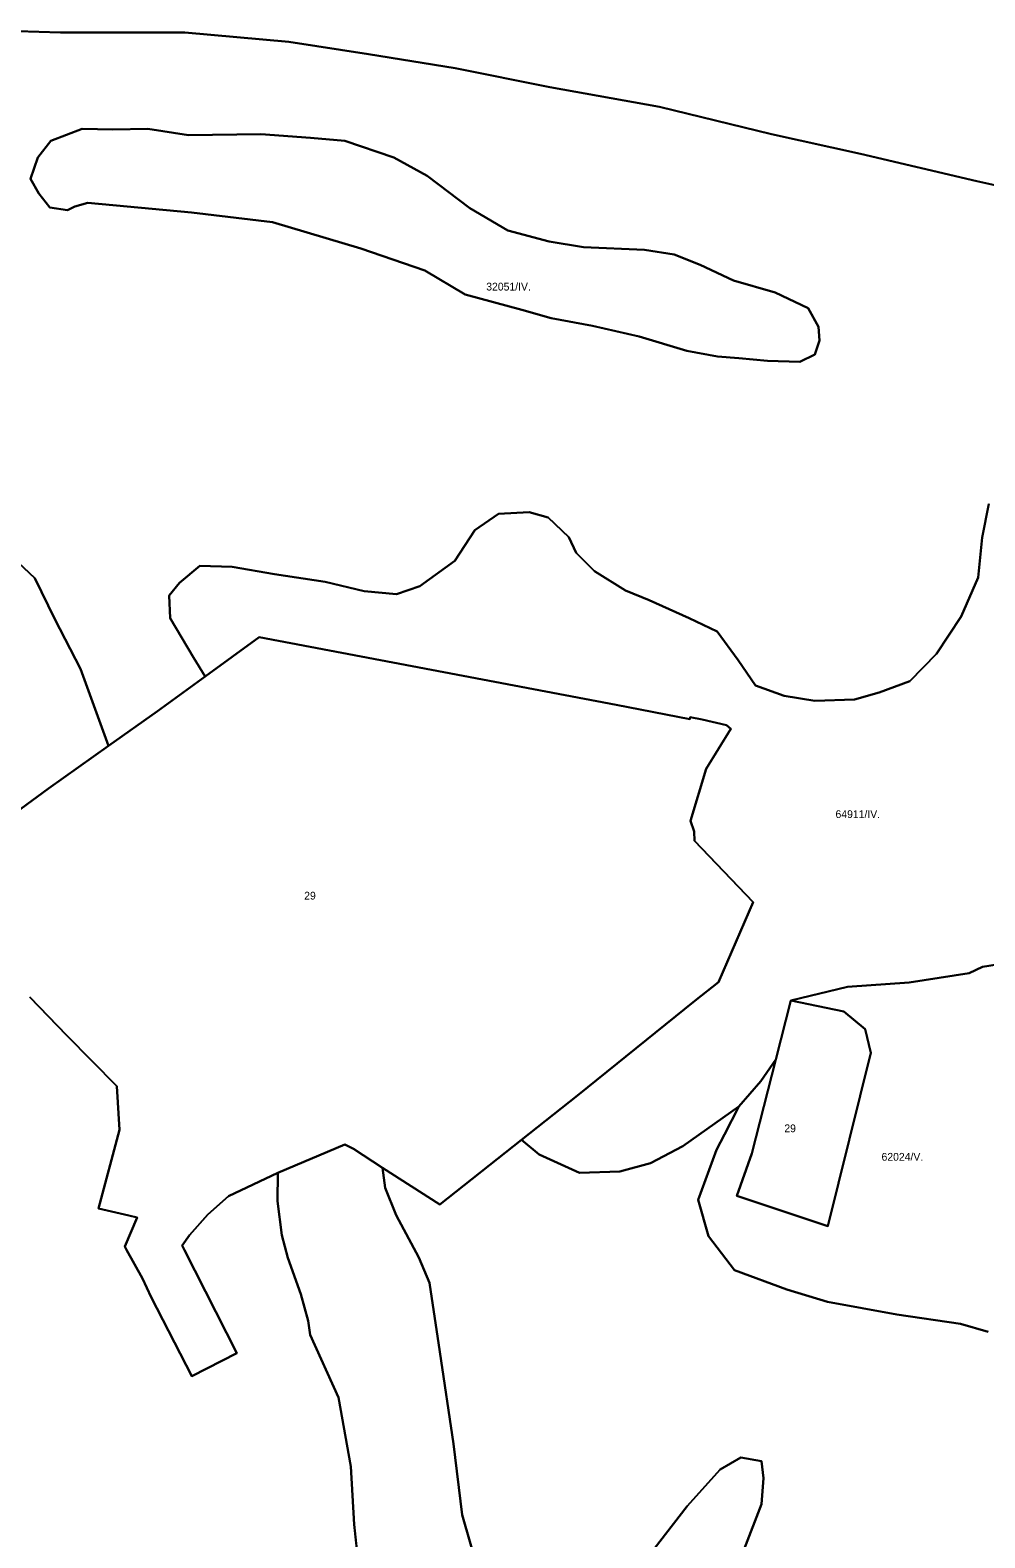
# Model space of a CAD drawing. Extents: x -521621 to -516761, y -1190184 to -1184927.
# Drawn here: x -519813 to -519322, y -1188092 to -1187318 of the extents above; entities that cross this region are included whole.
import ezdxf

# ---------------------------------------------------------------- set-up
doc = ezdxf.new("R2010")
doc.units = 0
doc.layers.add('BPEJ_s', color=7, linetype='Continuous')

msp = doc.modelspace()

# ---------------------------------------------------------------- linework, layer by layer
at = {"layer": 'BPEJ_s'}
for p, q in [((-519836.59, -1187317.66), (-519797.22, -1187318.93)), ((-519797.22, -1187318.93), (-519733.29, -1187318.93)), ((-519733.29, -1187318.93), (-519679.94, -1187323.59)), ((-519679.94, -1187323.59), (-519638.88, -1187329.95)), ((-519638.88, -1187329.95), (-519594.42, -1187337.15)), ((-519594.42, -1187337.15), (-519545.74, -1187346.89)), ((-519545.74, -1187346.89), (-519489.43, -1187357.06)), ((-519489.43, -1187357.06), (-519431.85, -1187371.04)), ((-519802.18, -1187374.46), (-519808.84, -1187383.02)), ((-519786.03, -1187368.28), (-519802.18, -1187374.46)), ((-519770.35, -1187368.75), (-519786.03, -1187368.28)), ((-519752.29, -1187368.28), (-519770.35, -1187368.75)), ((-519731.38, -1187371.61), (-519752.29, -1187368.28)), ((-519694.32, -1187371.13), (-519731.38, -1187371.61)), ((-519668.66, -1187373.03), (-519694.32, -1187371.13)), ((-519651.08, -1187374.46), (-519668.66, -1187373.03)), ((-519625.89, -1187383.02), (-519651.08, -1187374.46)), ((-519431.85, -1187371.04), (-519386.13, -1187381.21)), ((-519808.84, -1187383.02), (-519812.64, -1187393.96)), ((-519608.78, -1187392.53), (-519625.89, -1187383.02)), ((-519386.13, -1187381.21), (-519326.43, -1187395.19)), ((-519812.64, -1187393.96), (-519808.36, -1187401.56)), ((-519586.93, -1187409.17), (-519608.78, -1187392.53)), ((-519326.43, -1187395.19), (-519257, -1187410.86)), ((-519808.36, -1187401.56), (-519802.66, -1187408.69)), ((-519802.66, -1187408.69), (-519793.63, -1187410.12)), ((-519793.63, -1187410.12), (-519789.83, -1187408.22)), ((-519789.83, -1187408.22), (-519783.04, -1187406.37)), ((-519783.04, -1187406.37), (-519729.87, -1187411.26)), ((-519729.87, -1187411.26), (-519688.33, -1187416.31)), ((-519567.44, -1187420.58), (-519586.93, -1187409.17)), ((-519688.33, -1187416.31), (-519642.89, -1187429.9)), ((-519546.06, -1187426.29), (-519567.44, -1187420.58)), ((-519528.48, -1187429.14), (-519546.06, -1187426.29)), ((-519497.12, -1187430.57), (-519528.48, -1187429.14)), ((-519642.89, -1187429.9), (-519610.01, -1187441.1)), ((-519481.91, -1187432.94), (-519497.12, -1187430.57)), ((-519468.6, -1187438.17), (-519481.91, -1187432.94)), ((-519610.01, -1187441.1), (-519589.34, -1187453.42)), ((-519451.5, -1187446.26), (-519468.6, -1187438.17)), ((-519430.11, -1187452.44), (-519451.5, -1187446.26)), ((-519413.01, -1187460.52), (-519430.11, -1187452.44)), ((-519589.34, -1187453.42), (-519560.09, -1187461.28)), ((-519407.78, -1187470.03), (-519413.01, -1187460.52)), ((-519560.09, -1187461.28), (-519545.1, -1187465.54)), ((-519545.1, -1187465.54), (-519523.8, -1187469.49)), ((-519523.8, -1187469.49), (-519499.82, -1187475.02)), ((-519499.82, -1187475.02), (-519475.49, -1187482.38)), ((-519407.31, -1187477.16), (-519407.78, -1187470.03)), ((-519475.49, -1187482.38), (-519459.58, -1187485.25)), ((-519409.68, -1187484.3), (-519407.31, -1187477.16)), ((-519459.58, -1187485.25), (-519448.65, -1187486.2)), ((-519448.65, -1187486.2), (-519433.92, -1187487.62)), ((-519433.92, -1187487.62), (-519417.28, -1187488.1)), ((-519417.28, -1187488.1), (-519409.68, -1187484.3)), ((-519320.31, -1187560.93), (-519323.61, -1187578.33)), ((-519572.15, -1187566.12), (-519584.35, -1187574.45)), ((-519556.33, -1187565.29), (-519572.15, -1187566.12)), ((-519546.63, -1187568.06), (-519556.33, -1187565.29)), ((-519536.09, -1187578.06), (-519546.63, -1187568.06)), ((-519584.35, -1187574.45), (-519594.61, -1187590.27)), ((-519532.2, -1187586.11), (-519536.09, -1187578.06)), ((-519323.61, -1187578.33), (-519325.83, -1187598.87)), ((-519810.41, -1187599.15), (-519824.56, -1187585.83)), ((-519594.61, -1187590.27), (-519612.64, -1187603.31)), ((-519522.77, -1187595.54), (-519532.2, -1187586.11)), ((-519800.15, -1187620.24), (-519810.41, -1187599.15)), ((-519725.54, -1187592.77), (-519736.07, -1187601.65)), ((-519708.89, -1187593.32), (-519725.54, -1187592.77)), ((-519687.26, -1187597.21), (-519708.89, -1187593.32)), ((-519661.18, -1187601.09), (-519687.26, -1187597.21)), ((-519506.96, -1187605.53), (-519522.77, -1187595.54)), ((-519325.83, -1187598.87), (-519334.43, -1187618.86)), ((-519736.07, -1187601.65), (-519741.34, -1187608.03)), ((-519641.21, -1187605.81), (-519661.18, -1187601.09)), ((-519624.57, -1187607.48), (-519641.21, -1187605.81)), ((-519612.64, -1187603.31), (-519624.57, -1187607.48)), ((-519494.76, -1187610.53), (-519506.96, -1187605.53)), ((-519741.34, -1187608.03), (-519740.79, -1187619.69)), ((-519474.23, -1187619.69), (-519494.76, -1187610.53)), ((-519786.83, -1187645.78), (-519800.15, -1187620.24)), ((-519740.79, -1187619.69), (-519728.86, -1187639.95)), ((-519459.81, -1187626.63), (-519474.23, -1187619.69)), ((-519334.43, -1187618.86), (-519347.19, -1187638.01)), ((-519448.99, -1187641.34), (-519459.81, -1187626.63)), ((-519347.19, -1187638.01), (-519360.78, -1187652.16)), ((-519772.51, -1187685.38), (-519786.83, -1187645.78)), ((-519728.86, -1187639.95), (-519722.87, -1187649.69)), ((-519440.11, -1187654.38), (-519448.99, -1187641.34)), ((-519722.87, -1187649.69), (-519747.38, -1187667.46)), ((-519360.78, -1187652.16), (-519376.59, -1187657.99)), ((-519425.41, -1187659.66), (-519440.11, -1187654.38)), ((-519409.6, -1187662.15), (-519425.41, -1187659.66)), ((-519389.35, -1187661.6), (-519409.6, -1187662.15)), ((-519376.59, -1187657.99), (-519389.35, -1187661.6)), ((-519747.38, -1187667.46), (-519772.51, -1187685.38)), ((-519812.86, -1187814.51), (-519793.87, -1187834.17)), ((-519793.87, -1187834.17), (-519768.25, -1187860.13)), ((-519768.25, -1187860.13), (-519766.91, -1187882.58)), ((-519766.91, -1187882.58), (-519777.62, -1187923.04)), ((-519710.91, -1187916.7), (-519685.53, -1187904.73)), ((-519685.53, -1187904.73), (-519685.65, -1187919.2)), ((-519721.39, -1187926.04), (-519710.91, -1187916.7)), ((-519777.62, -1187923.04), (-519761.98, -1187926.53)), ((-519685.65, -1187919.2), (-519683.42, -1187936.76)), ((-519757.81, -1187927.71), (-519764.18, -1187942.61)), ((-519761.98, -1187926.53), (-519757.81, -1187927.71)), ((-519730.89, -1187936.69), (-519721.39, -1187926.04)), ((-519734.58, -1187942.03), (-519730.89, -1187936.69)), ((-519683.42, -1187936.76), (-519680.31, -1187948.33)), ((-519764.18, -1187942.61), (-519763.17, -1187944.17)), ((-519763.17, -1187944.17), (-519755.07, -1187958.91)), ((-519733.51, -1187944.38), (-519734.58, -1187942.03)), ((-519706.62, -1187997.35), (-519733.51, -1187944.38)), ((-519680.31, -1187948.33), (-519673.65, -1187967)), ((-519755.07, -1187958.91), (-519750.58, -1187968.52)), ((-519750.58, -1187968.52), (-519729.67, -1188009.1)), ((-519673.65, -1187967), (-519669.87, -1187980.79)), ((-519669.87, -1187980.79), (-519668.9, -1187987.88)), ((-519668.9, -1187987.88), (-519654.42, -1188020.09)), ((-519729.67, -1188009.1), (-519706.62, -1187997.35)), ((-519654.42, -1188020.09), (-519647.98, -1188055.52)), ((-519647.98, -1188055.52), (-519646.37, -1188085.32)), ((-519646.37, -1188085.32), (-519639.13, -1188151.35))]:
    msp.add_line(p, q, dxfattribs=at)
for points in [[(-519257, -1187410.86), (-519326.43, -1187395.19), (-519386.13, -1187381.21), (-519431.85, -1187371.04), (-519489.43, -1187357.06), (-519545.74, -1187346.89), (-519594.42, -1187337.15), (-519638.88, -1187329.95), (-519679.94, -1187323.59), (-519733.29, -1187318.93), (-519797.22, -1187318.93), (-519836.59, -1187317.66)], [(-519303.15, -1187795.52), (-519323.47, -1187798.9), (-519330.33, -1187802.04), (-519361.24, -1187806.96), (-519392.85, -1187809.07), (-519422.03, -1187816.17), (-519429.72, -1187846.45), (-519437.46, -1187857.57), (-519448.7, -1187870.58), (-519477.51, -1187890.97), (-519494.02, -1187899.75), (-519509.82, -1187903.97), (-519530.55, -1187904.67), (-519551.27, -1187895.18), (-519560.37, -1187887.81), (-519531.55, -1187865), (-519471.37, -1187816.27), (-519459.2, -1187806.79), (-519441.4, -1187765.6), (-519471.42, -1187734.06), (-519471.72, -1187729.26), (-519473.52, -1187723.85), (-519465.47, -1187697.1), (-519452.88, -1187676.55), (-519455.1, -1187674.65), (-519467.57, -1187671.74), (-519473.61, -1187670.59), (-519473.79, -1187671.56), (-519511.79, -1187664.33), (-519695.16, -1187629.58), (-519722.87, -1187649.69), (-519728.86, -1187639.95), (-519740.79, -1187619.69), (-519741.34, -1187608.03), (-519736.07, -1187601.65), (-519725.54, -1187592.77), (-519708.89, -1187593.32), (-519687.26, -1187597.21), (-519661.18, -1187601.09), (-519641.21, -1187605.81), (-519624.57, -1187607.48), (-519612.64, -1187603.31), (-519594.61, -1187590.27), (-519584.35, -1187574.45), (-519572.15, -1187566.12), (-519556.33, -1187565.29), (-519546.63, -1187568.06), (-519536.09, -1187578.06), (-519532.2, -1187586.11), (-519522.77, -1187595.54), (-519506.96, -1187605.53), (-519494.76, -1187610.53), (-519474.23, -1187619.69), (-519459.81, -1187626.63), (-519448.99, -1187641.34), (-519440.11, -1187654.38), (-519425.41, -1187659.66), (-519409.6, -1187662.15), (-519389.35, -1187661.6), (-519376.59, -1187657.99), (-519360.78, -1187652.16), (-519347.19, -1187638.01), (-519334.43, -1187618.86), (-519325.83, -1187598.87), (-519323.61, -1187578.33), (-519320.31, -1187560.93)], [(-519824.56, -1187585.83), (-519810.41, -1187599.15), (-519800.15, -1187620.24), (-519786.83, -1187645.78), (-519772.51, -1187685.38), (-519803.25, -1187707.28), (-519826, -1187723.77)], [(-519826, -1187723.77), (-519803.25, -1187707.28), (-519772.51, -1187685.38), (-519747.38, -1187667.46), (-519722.87, -1187649.69), (-519695.16, -1187629.58), (-519511.79, -1187664.33), (-519473.79, -1187671.56), (-519473.61, -1187670.59), (-519467.57, -1187671.74), (-519455.1, -1187674.65), (-519452.88, -1187676.55), (-519465.47, -1187697.1), (-519473.52, -1187723.85), (-519471.72, -1187729.26), (-519471.42, -1187734.06), (-519441.4, -1187765.6), (-519459.2, -1187806.79), (-519471.37, -1187816.27), (-519531.55, -1187865), (-519560.37, -1187887.81), (-519602.33, -1187921.01), (-519631.66, -1187902.09), (-519646.68, -1187892.41), (-519651.15, -1187890.15), (-519685.53, -1187904.73), (-519710.91, -1187916.7), (-519721.39, -1187926.04), (-519730.89, -1187936.69), (-519734.58, -1187942.03), (-519733.51, -1187944.38), (-519706.62, -1187997.35), (-519729.67, -1188009.1), (-519750.58, -1187968.52), (-519755.07, -1187958.91), (-519763.17, -1187944.17), (-519764.18, -1187942.61), (-519757.81, -1187927.71), (-519761.98, -1187926.53), (-519777.62, -1187923.04), (-519766.91, -1187882.58), (-519768.25, -1187860.13), (-519793.87, -1187834.17), (-519812.86, -1187814.51)], [(-519320.55, -1187986.31), (-519334.84, -1187982.22), (-519367.49, -1187977.41), (-519403.06, -1187970.99), (-519424.06, -1187964.57), (-519450.88, -1187954.65), (-519464.29, -1187937.15), (-519469.54, -1187918.48), (-519460.21, -1187892.8), (-519456.08, -1187884.99), (-519448.7, -1187870.58), (-519437.46, -1187857.57), (-519429.72, -1187846.45), (-519441.99, -1187894.78), (-519449.8, -1187916.5), (-519402.93, -1187932.13), (-519380.8, -1187843.1), (-519383.84, -1187830.94), (-519394.69, -1187821.82), (-519422.03, -1187816.17), (-519392.85, -1187809.07), (-519361.24, -1187806.96), (-519330.33, -1187802.04), (-519323.47, -1187798.9), (-519303.15, -1187795.52)], [(-519581.87, -1188111.43), (-519590.76, -1188080.3), (-519595.2, -1188043.83), (-519602.31, -1187996.69), (-519607.65, -1187961.11), (-519613.1, -1187948.26), (-519624.69, -1187926.47), (-519630.31, -1187912.41), (-519631.66, -1187902.09), (-519602.33, -1187921.01), (-519560.37, -1187887.81), (-519551.27, -1187895.18), (-519530.55, -1187904.67), (-519509.82, -1187903.97), (-519494.02, -1187899.75), (-519477.51, -1187890.97), (-519448.7, -1187870.58), (-519456.08, -1187884.99), (-519460.21, -1187892.8), (-519469.54, -1187918.48), (-519464.29, -1187937.15), (-519450.88, -1187954.65), (-519424.06, -1187964.57), (-519403.06, -1187970.99), (-519367.49, -1187977.41), (-519334.84, -1187982.22), (-519320.55, -1187986.31)], [(-519639.13, -1188151.35), (-519646.37, -1188085.32), (-519647.98, -1188055.52), (-519654.42, -1188020.09), (-519668.9, -1187987.88), (-519669.87, -1187980.79), (-519673.65, -1187967), (-519680.31, -1187948.33), (-519683.42, -1187936.76), (-519685.65, -1187919.2), (-519685.53, -1187904.73), (-519651.15, -1187890.15), (-519646.68, -1187892.41), (-519631.66, -1187902.09), (-519630.31, -1187912.41), (-519624.69, -1187926.47), (-519613.1, -1187948.26), (-519607.65, -1187961.11), (-519602.31, -1187996.69), (-519595.2, -1188043.83), (-519590.76, -1188080.3), (-519581.87, -1188111.43)], [(-519445.87, -1188098.08), (-519436.98, -1188074.96), (-519436.09, -1188061.62), (-519436.98, -1188052.72), (-519447.65, -1188050.95), (-519458.31, -1188057.17), (-519475.2, -1188075.85), (-519499.2, -1188106.98)], [(-519499.2, -1188106.98), (-519475.2, -1188075.85), (-519458.31, -1188057.17), (-519447.65, -1188050.95), (-519436.98, -1188052.72), (-519436.09, -1188061.62), (-519436.98, -1188074.96), (-519445.87, -1188098.08)]]:
    msp.add_lwpolyline(points, dxfattribs=at)
for points in [[(-519770.35, -1187368.75), (-519752.29, -1187368.28), (-519731.38, -1187371.61), (-519694.32, -1187371.13), (-519668.66, -1187373.03), (-519651.08, -1187374.46), (-519625.89, -1187383.02), (-519608.78, -1187392.53), (-519586.93, -1187409.17), (-519567.44, -1187420.58), (-519546.06, -1187426.29), (-519528.48, -1187429.14), (-519497.12, -1187430.57), (-519481.91, -1187432.94), (-519468.6, -1187438.17), (-519451.5, -1187446.26), (-519430.11, -1187452.44), (-519413.01, -1187460.52), (-519407.78, -1187470.03), (-519407.31, -1187477.16), (-519409.68, -1187484.3), (-519417.28, -1187488.1), (-519433.92, -1187487.62), (-519448.65, -1187486.2), (-519459.58, -1187485.25), (-519475.49, -1187482.38), (-519499.82, -1187475.02), (-519523.8, -1187469.49), (-519545.1, -1187465.54), (-519560.09, -1187461.28), (-519589.34, -1187453.42), (-519610.01, -1187441.1), (-519642.89, -1187429.9), (-519688.33, -1187416.31), (-519729.87, -1187411.26), (-519783.04, -1187406.37), (-519789.83, -1187408.22), (-519793.63, -1187410.12), (-519802.66, -1187408.69), (-519808.36, -1187401.56), (-519812.64, -1187393.96), (-519808.84, -1187383.02), (-519802.18, -1187374.46), (-519786.03, -1187368.28)], [(-519429.72, -1187846.45), (-519422.03, -1187816.17), (-519394.69, -1187821.82), (-519383.84, -1187830.94), (-519380.8, -1187843.1), (-519402.93, -1187932.13), (-519449.8, -1187916.5), (-519441.99, -1187894.78)]]:
    msp.add_lwpolyline(points, close=True, dxfattribs=at)

# ---------------------------------------------------------------- texts
for s, p in [('32051/IV.', (-519578.45, -1187451.42)), ('64911/IV.', (-519399.03, -1187722.42)), ('29', (-519671.97, -1187764.3)), ('29', (-519425.31, -1187883.82)), ('62024/V.', (-519375.39, -1187898.46))]:
    msp.add_text(s, height=4, dxfattribs=at).set_placement(p)

doc.saveas('drawing.dxf')
